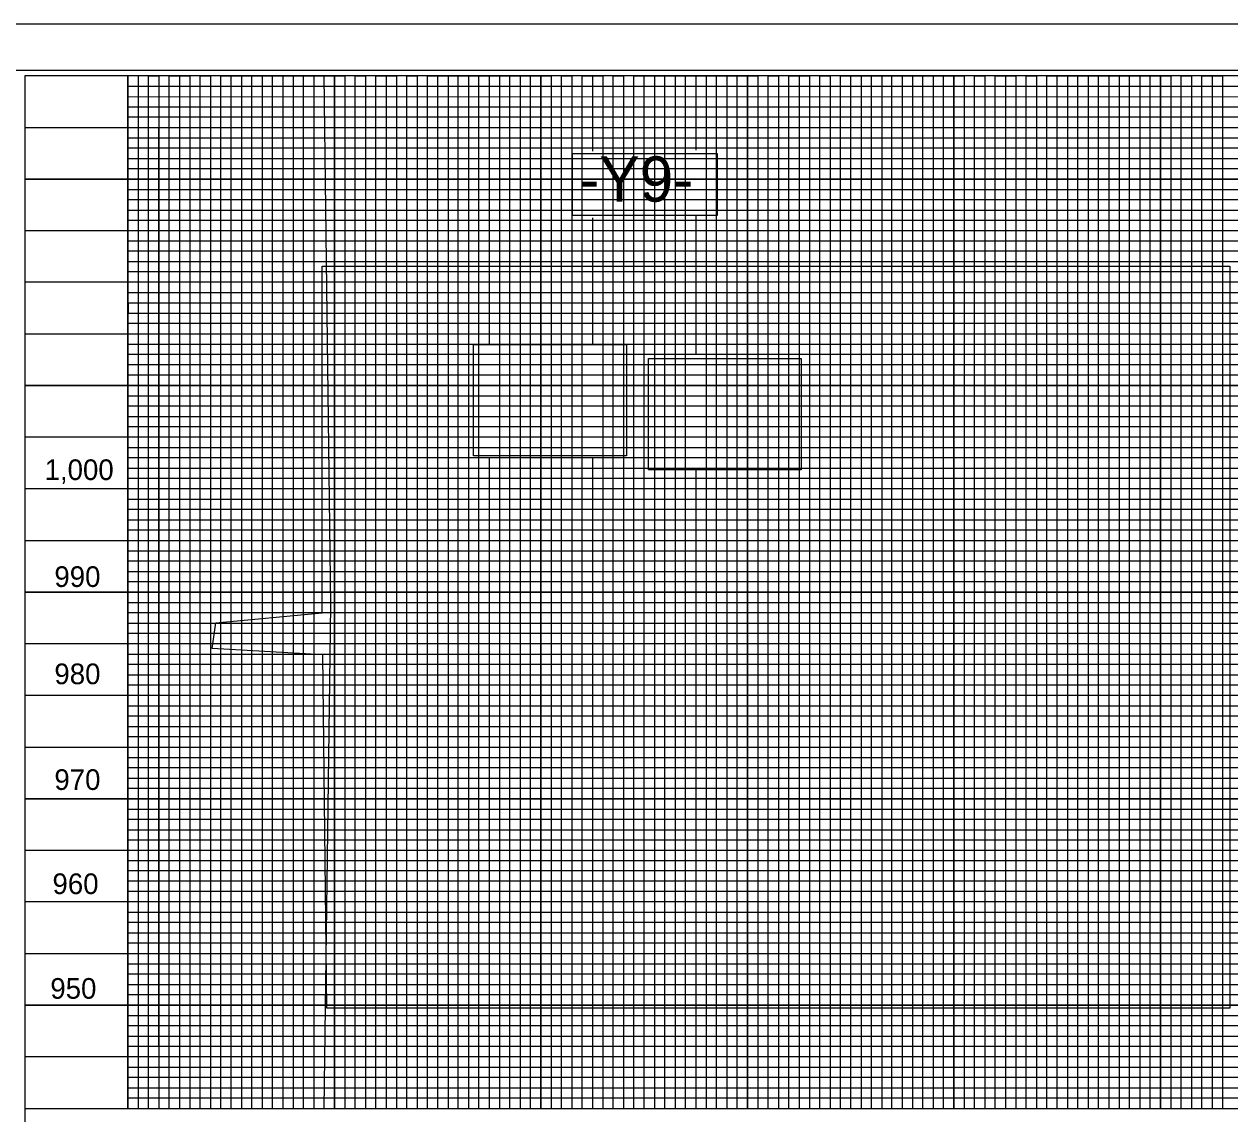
# Model space of a CAD drawing. Extents: x 1628636 to 1631253, y 896159 to 897520.
# Drawn here: x 1629226 to 1629810, y 896731 to 897259 of the extents above; entities that cross this region are included whole.
import ezdxf

# ---------------------------------------------------------------- set-up
doc = ezdxf.new("R2010")
doc.units = 0
for name, color, linetype in [('Prop DSN Text', 7, 'Continuous'), ('Prop PHM Black Shape', 7, 'Continuous'), ('Scratch_Level_6', 7, 'Continuous'), ('Sheet Cutting Line CELL', 7, 'Continuous'), ('Sheet DOT Grid CELL', 7, 'Continuous'), ('Sheet Layout Profile Border Port 1', 7, 'Continuous'), ('Sheet Plot Border Inside CELL', 7, 'Continuous'), ('Sheet Plot Border Outside CELL', 7, 'Continuous'), ('Sheet Profile CELL', 7, 'Continuous'), ('Sheet Profile Grid Major CELL', 7, 'Continuous'), ('Sheet Profile Grid Middle CELL', 7, 'Continuous'), ('Sheet Profile Grid Minor CELL', 7, 'Continuous')]:
    doc.layers.add(name, color=color, linetype=linetype)

msp = doc.modelspace()

# ---------------------------------------------------------------- linework, layer by layer
at = {"layer": 'Prop PHM Black Shape'}
for points in [[(1629491.77, 897196.22), (1629561.77, 897196.22), (1629561.77, 897166.22), (1629491.77, 897166.22)], [(1629443.84, 897103.79), (1629517.89, 897103.79), (1629517.89, 897049.92), (1629443.84, 897049.92)], [(1629528.51, 897096.99), (1629602.56, 897096.99), (1629602.56, 897043.11), (1629528.51, 897043.11)]]:
    msp.add_lwpolyline(points, close=True, dxfattribs=at)
at = {"layer": 'Scratch_Level_6'}
for points in [[(1629291.5, 897208.9), (1629781.5, 897208.9), (1629781.5, 896763.9), (1629291.5, 896763.9)], [(1629370.86, 896953.54), (1629317.29, 896956.57), (1629319.12, 896969.06), (1629370.56, 896973.83), (1629370.56, 897141.7), (1629810.05, 897141.7), (1629810.05, 896782.51), (1629372.86, 896782.51)]]:
    msp.add_lwpolyline(points, close=True, dxfattribs=at)
at = {"layer": 'Sheet Cutting Line CELL'}
msp.add_line((1630743.5, 897258.9), (1629059.5, 897258.9), dxfattribs=at)
at = {"layer": 'Sheet DOT Grid CELL'}
for p, q in [((1629276.5, 896733.9), (1629276.5, 897233.9)), ((1629326.5, 896733.9), (1629326.5, 897233.9)), ((1629376.5, 896733.9), (1629376.5, 897233.9)), ((1629426.5, 896733.9), (1629426.5, 897233.9)), ((1629476.5, 896733.9), (1629476.5, 897233.9)), ((1629526.5, 896733.9), (1629526.5, 897233.9)), ((1629576.5, 896733.9), (1629576.5, 897233.9)), ((1629626.5, 896733.9), (1629626.5, 897233.9)), ((1629676.5, 896733.9), (1629676.5, 897233.9)), ((1629726.5, 896733.9), (1629726.5, 897233.9)), ((1629776.5, 896733.9), (1629776.5, 897233.9)), ((1630526.45, 897183.9), (1629226.5, 897183.9)), ((1630526.45, 897133.9), (1629226.5, 897133.9)), ((1630526.5, 897083.9), (1629226.5, 897083.9)), ((1630726.5, 897033.9), (1629226.5, 897033.9)), ((1630726.5, 896983.9), (1629226.5, 896983.9)), ((1630726.5, 896933.9), (1629226.5, 896933.9)), ((1630726.5, 896883.9), (1629226.5, 896883.9)), ((1630726.5, 896833.9), (1629226.5, 896833.9)), ((1630726.5, 896783.9), (1629226.5, 896783.9))]:
    msp.add_line(p, q, dxfattribs=at)
at = {"layer": 'Sheet Layout Profile Border Port 1'}
msp.add_lwpolyline([(1629276.5, 897072.85), (1629276.5, 896733.9), (1630676.5, 896733.9), (1630676.5, 897072.85)], dxfattribs=at)
at = {"layer": 'Sheet Plot Border Inside CELL'}
msp.add_lwpolyline([(1629072.5, 896181.35), (1630739, 896181.35), (1630739, 897236.45), (1629072.5, 897236.45)], close=True, dxfattribs=at)
at = {"layer": 'Sheet Plot Border Outside CELL'}
msp.add_lwpolyline([(1629059.5, 896158.9), (1630743.5, 896158.9), (1630743.5, 897258.9), (1629059.5, 897258.9)], close=True, dxfattribs=at)
at = {"layer": 'Sheet Profile CELL'}
msp.add_line((1629226.5, 896733.9), (1630726.5, 896733.9), dxfattribs=at)
msp.add_lwpolyline([(1630726.5, 897233.9), (1629226.5, 897233.9), (1629226.5, 896183.9), (1630726.5, 896183.9)], close=True, dxfattribs=at)
at = {"layer": 'Sheet Profile Grid Major CELL'}
for points in [[(1629276.5, 897233.9), (1629276.5, 896733.9), (1629326.5, 896733.9), (1629326.5, 897233.9), (1629376.5, 897233.9), (1629376.5, 896733.9), (1629426.5, 896733.9), (1629426.5, 897233.9), (1629476.5, 897233.9), (1629476.5, 896733.9), (1629526.5, 896733.9), (1629526.5, 897233.9), (1629576.5, 897233.9), (1629576.5, 896733.9), (1629626.5, 896733.9), (1629626.5, 897233.9), (1629676.5, 897233.9), (1629676.5, 896733.9), (1629726.5, 896733.9), (1629726.5, 897233.9), (1629776.5, 897233.9), (1629776.5, 896733.9), (1629826.5, 896733.9)], [(1629226.5, 897183.9), (1630526.5, 897183.9)], [(1630526.5, 897133.9), (1629226.5, 897133.9), (1629226.5, 897083.9), (1630526.5, 897083.9)], [(1630726.5, 897033.9), (1629226.5, 897033.9), (1629226.5, 896983.9), (1630726.5, 896983.9)], [(1630726.5, 896933.9), (1629226.5, 896933.9), (1629226.5, 896883.9), (1630726.5, 896883.9)], [(1630726.5, 896833.9), (1629226.5, 896833.9), (1629226.5, 896833.9), (1629226.5, 896783.9), (1630726.5, 896783.9)]]:
    msp.add_lwpolyline(points, dxfattribs=at)
at = {"layer": 'Sheet Profile Grid Middle CELL'}
msp.add_line((1629226.5, 897208.9), (1630526.45, 897208.9), dxfattribs=at)
for points in [[(1630526.5, 897158.9), (1629226.5, 897158.9), (1629226.5, 897108.9), (1630526.5, 897108.9)], [(1630098.37, 897058.9), (1629226.5, 897058.9), (1629226.5, 897008.9), (1630551.5, 897008.9)], [(1630726.5, 896958.9), (1629226.5, 896958.9), (1629226.5, 896908.9), (1630726.5, 896908.9)], [(1630726.5, 896858.9), (1629226.5, 896858.9), (1629226.5, 896808.9), (1630726.5, 896808.9)], [(1630726.5, 896758.9), (1629226.5, 896758.9)]]:
    msp.add_lwpolyline(points, dxfattribs=at)
at = {"layer": 'Sheet Profile Grid Minor CELL'}
for p, q in [((1629281.5, 897233.9), (1629281.5, 896733.9)), ((1629286.5, 896733.9), (1629286.5, 897233.9)), ((1629286.5, 897233.9), (1629291.5, 897233.9)), ((1629291.5, 897233.9), (1629291.5, 896733.9)), ((1629296.5, 896733.9), (1629296.5, 897233.9)), ((1629296.5, 897233.9), (1629306.5, 897233.9)), ((1629301.5, 897233.9), (1629301.5, 896733.9)), ((1629306.5, 897233.9), (1629306.5, 896733.9)), ((1629311.5, 896733.9), (1629311.5, 897233.9)), ((1629311.5, 897233.9), (1629316.5, 897233.9)), ((1629316.5, 897233.9), (1629316.5, 896733.9)), ((1629336.5, 896733.9), (1629336.5, 897233.9)), ((1629336.5, 897233.9), (1629341.5, 897233.9)), ((1629341.5, 897233.9), (1629341.5, 896733.9)), ((1629346.5, 896733.9), (1629346.5, 897233.9)), ((1629346.5, 897233.9), (1629356.5, 897233.9)), ((1629351.5, 897233.9), (1629351.5, 896733.9)), ((1629356.5, 897233.9), (1629356.5, 896733.9)), ((1629361.5, 896733.9), (1629361.5, 897233.9)), ((1629361.5, 897233.9), (1629366.5, 897233.9)), ((1629366.5, 897233.9), (1629366.5, 896733.9)), ((1629371.5, 897233.9), (1629381.5, 897233.9)), ((1629381.5, 897233.9), (1629381.5, 896733.9)), ((1629386.5, 896733.9), (1629386.5, 897233.9)), ((1629386.5, 897233.9), (1629391.5, 897233.9)), ((1629391.5, 897233.9), (1629391.5, 896733.9)), ((1629396.5, 896733.9), (1629396.5, 897233.9)), ((1629396.5, 897233.9), (1629406.5, 897233.9)), ((1629401.5, 897233.9), (1629401.5, 896733.9)), ((1629406.5, 897233.9), (1629406.5, 896733.9)), ((1629411.5, 896733.9), (1629411.5, 897233.9)), ((1629411.5, 897233.9), (1629416.5, 897233.9)), ((1629416.5, 897233.9), (1629416.5, 896733.9)), ((1629421.5, 896733.9), (1629421.5, 897233.9)), ((1629421.5, 897233.9), (1629431.5, 897233.9)), ((1629431.5, 897233.9), (1629431.5, 896733.9)), ((1629436.5, 896733.9), (1629436.5, 897233.9)), ((1629436.5, 897233.9), (1629441.5, 897233.9)), ((1629441.5, 897233.9), (1629441.5, 896733.9)), ((1629446.5, 896733.9), (1629446.5, 897233.9)), ((1629446.5, 897233.9), (1629456.5, 897233.9)), ((1629451.5, 897233.9), (1629451.5, 897103.9)), ((1629456.5, 897233.9), (1629456.5, 896733.9)), ((1629461.5, 896733.9), (1629461.5, 897233.9)), ((1629461.5, 897233.9), (1629466.5, 897233.9)), ((1629466.5, 897233.9), (1629466.5, 896733.9)), ((1629471.5, 896733.9), (1629471.5, 897233.9)), ((1629471.5, 897233.9), (1629481.5, 897233.9)), ((1629481.5, 897233.9), (1629481.5, 896733.9)), ((1629486.5, 896733.9), (1629486.5, 897233.9)), ((1629486.5, 897233.9), (1629491.5, 897233.9)), ((1629491.5, 897233.9), (1629491.5, 896733.9)), ((1629496.5, 896733.9), (1629496.5, 897233.9)), ((1629496.5, 897233.9), (1629506.5, 897233.9)), ((1629501.5, 897233.9), (1629501.5, 897197.38)), ((1629506.5, 897233.9), (1629506.5, 896733.9)), ((1629511.5, 896733.9), (1629511.5, 897233.9)), ((1629511.5, 897233.9), (1629516.5, 897233.9)), ((1629516.5, 897233.9), (1629516.5, 896733.9)), ((1629521.5, 896733.9), (1629521.5, 897233.9)), ((1629521.5, 897233.9), (1629531.5, 897233.9)), ((1629531.5, 897233.9), (1629531.5, 896733.9)), ((1629536.5, 896733.9), (1629536.5, 897233.9)), ((1629536.5, 897233.9), (1629541.5, 897233.9)), ((1629541.5, 897233.9), (1629541.5, 896733.9)), ((1629546.5, 896733.9), (1629546.5, 897233.9)), ((1629546.5, 897233.9), (1629556.5, 897233.9)), ((1629551.5, 897233.9), (1629551.5, 897197.9)), ((1629556.5, 897233.9), (1629556.5, 896733.9)), ((1629561.5, 896733.9), (1629561.5, 897233.9)), ((1629561.5, 897233.9), (1629566.5, 897233.9)), ((1629566.5, 897233.9), (1629566.5, 896733.9)), ((1629571.5, 896733.9), (1629571.5, 897233.9)), ((1629571.5, 897233.9), (1629581.5, 897233.9)), ((1629581.5, 897233.9), (1629581.5, 896733.9)), ((1629586.5, 896733.9), (1629586.5, 897233.9)), ((1629586.5, 897233.9), (1629591.5, 897233.9)), ((1629591.5, 897233.9), (1629591.5, 896733.9)), ((1629596.5, 896733.9), (1629596.5, 897233.9)), ((1629596.5, 897233.9), (1629606.5, 897233.9)), ((1629601.5, 897233.9), (1629601.5, 896733.9)), ((1629606.5, 897233.9), (1629606.5, 896733.9)), ((1629611.5, 896733.9), (1629611.5, 897233.9)), ((1629611.5, 897233.9), (1629616.5, 897233.9)), ((1629616.5, 897233.9), (1629616.5, 896733.9)), ((1629621.5, 896733.9), (1629621.5, 897233.9)), ((1629621.5, 897233.9), (1629631.5, 897233.9)), ((1629631.5, 897233.9), (1629631.5, 896733.9)), ((1629636.5, 896733.9), (1629636.5, 897233.9)), ((1629636.5, 897233.9), (1629641.5, 897233.9)), ((1629641.5, 897233.9), (1629641.5, 896733.9)), ((1629646.5, 896733.9), (1629646.5, 897233.9)), ((1629646.5, 897233.9), (1629656.5, 897233.9)), ((1629651.5, 897233.9), (1629651.5, 896733.9)), ((1629656.5, 897233.9), (1629656.5, 896733.9)), ((1629661.5, 896733.9), (1629661.5, 897233.9)), ((1629661.5, 897233.9), (1629666.5, 897233.9)), ((1629666.5, 897233.9), (1629666.5, 896733.9)), ((1629671.5, 896733.9), (1629671.5, 897233.9)), ((1629671.5, 897233.9), (1629681.5, 897233.9)), ((1629681.5, 897233.9), (1629681.5, 896733.9)), ((1629686.5, 896733.9), (1629686.5, 897233.9)), ((1629686.5, 897233.9), (1629691.5, 897233.9)), ((1629691.5, 897233.9), (1629691.5, 896733.9)), ((1629696.5, 896733.9), (1629696.5, 897233.9)), ((1629696.5, 897233.9), (1629706.5, 897233.9)), ((1629701.5, 897233.9), (1629701.5, 896733.9)), ((1629706.5, 897233.9), (1629706.5, 896733.9)), ((1629711.5, 896733.9), (1629711.5, 897233.9)), ((1629711.5, 897233.9), (1629716.5, 897233.9)), ((1629716.5, 897233.9), (1629716.5, 896733.9)), ((1629721.5, 896733.9), (1629721.5, 897233.9)), ((1629721.5, 897233.9), (1629731.5, 897233.9)), ((1629731.5, 897233.9), (1629731.5, 896733.9)), ((1629736.5, 896733.9), (1629736.5, 897233.9)), ((1629736.5, 897233.9), (1629741.5, 897233.9)), ((1629741.5, 897233.9), (1629741.5, 896733.9)), ((1629746.5, 896733.9), (1629746.5, 897233.9)), ((1629746.5, 897233.9), (1629756.5, 897233.9)), ((1629751.5, 897233.9), (1629751.5, 896733.9)), ((1629756.5, 897233.9), (1629756.5, 896733.9)), ((1629761.5, 896733.9), (1629761.5, 897233.9)), ((1629761.5, 897233.9), (1629766.5, 897233.9)), ((1629766.5, 897233.9), (1629766.5, 896733.9)), ((1629771.5, 896733.9), (1629771.5, 897233.9)), ((1629771.5, 897233.9), (1629781.5, 897233.9)), ((1629781.5, 897233.9), (1629781.5, 896733.9)), ((1629786.5, 896733.9), (1629786.5, 897233.9)), ((1629786.5, 897233.9), (1629791.5, 897233.9)), ((1629791.5, 897233.9), (1629791.5, 896733.9)), ((1629796.5, 896733.9), (1629796.5, 897233.9)), ((1629796.5, 897233.9), (1629806.5, 897233.9)), ((1629801.5, 897233.9), (1629801.5, 896733.9)), ((1629806.5, 897233.9), (1629806.5, 896733.9)), ((1629276.5, 897228.9), (1630526.5, 897228.9)), ((1629276.5, 897223.9), (1629276.5, 897223.9)), ((1630526.5, 897223.9), (1629276.5, 897223.55)), ((1629276.5, 897218.9), (1630526.5, 897218.9)), ((1629501.5, 897165.19), (1629501.5, 897103.9)), ((1629551.5, 897166.23), (1629551.5, 897098.9)), ((1630526.45, 897098.9), (1629276.5, 897098.9)), ((1630526.5, 897093.9), (1629276.5, 897093.9)), ((1630101.43, 897088.9), (1629276.5, 897088.9)), ((1629276.5, 897078.9), (1630101.43, 897078.9)), ((1630101.43, 897073.9), (1629276.5, 897073.9)), ((1629276.5, 897068.9), (1630101.5, 897068.9)), ((1630101.43, 897048.9), (1629276.5, 897048.9)), ((1629451.5, 897048.9), (1629451.5, 896733.9)), ((1629501.5, 897048.97), (1629501.5, 896733.9)), ((1629276.5, 897043.9), (1630171.5, 897043.9)), ((1629551.5, 897043.9), (1629551.5, 896733.9)), ((1630676.5, 897023.9), (1629276.5, 897023.9)), ((1629276.5, 897018.9), (1630676.5, 897018.9)), ((1630676.5, 896998.9), (1629276.5, 896998.9)), ((1629276.5, 896993.9), (1630676.5, 896993.9)), ((1630676.5, 896988.9), (1629276.5, 896988.9)), ((1629276.5, 896978.9), (1630676.5, 896978.9)), ((1630676.5, 896973.9), (1629276.5, 896973.9)), ((1629276.5, 896968.9), (1630676.5, 896968.9)), ((1630676.5, 896963.9), (1629276.5, 896963.9)), ((1629276.5, 896953.9), (1630676.5, 896953.9)), ((1630676.5, 896948.9), (1629276.5, 896948.9)), ((1629276.5, 896943.9), (1630676.5, 896943.9)), ((1630676.5, 896938.9), (1629276.5, 896938.9)), ((1629276.5, 896928.9), (1630676.5, 896928.9)), ((1630676.5, 896923.9), (1629276.5, 896923.9)), ((1629276.5, 896918.9), (1630676.5, 896918.9)), ((1630676.5, 896913.9), (1629276.5, 896913.9)), ((1629276.5, 896903.9), (1630676.5, 896903.9)), ((1630676.5, 896898.9), (1629276.5, 896898.9)), ((1629276.5, 896893.9), (1630676.5, 896893.9)), ((1630676.5, 896888.9), (1629276.5, 896888.9)), ((1629276.5, 896878.9), (1630676.5, 896878.9)), ((1630676.5, 896873.9), (1629276.5, 896873.9)), ((1629276.5, 896868.9), (1630676.5, 896868.9)), ((1630676.5, 896863.9), (1629276.5, 896863.9)), ((1629276.5, 896853.9), (1630676.5, 896853.9)), ((1630676.5, 896848.9), (1629276.5, 896848.9)), ((1630676.5, 896843.9), (1629276.5, 896843.9)), ((1630676.5, 896838.9), (1629276.5, 896838.9)), ((1629276.5, 896828.9), (1630676.5, 896828.9)), ((1630676.5, 896823.9), (1629276.5, 896823.9)), ((1629276.5, 896818.9), (1630676.5, 896818.9)), ((1630676.5, 896813.9), (1629276.5, 896813.9)), ((1629276.5, 896803.9), (1630676.5, 896803.9)), ((1630676.5, 896798.9), (1629276.5, 896798.9)), ((1629276.5, 896793.9), (1630676.5, 896793.9)), ((1630676.5, 896788.9), (1629276.5, 896788.9)), ((1629276.5, 896778.9), (1630676.5, 896778.9)), ((1630676.5, 896773.9), (1629276.5, 896773.9)), ((1629276.5, 896768.9), (1630676.5, 896768.9)), ((1630676.5, 896763.9), (1629276.5, 896763.9)), ((1629276.5, 896753.9), (1630676.5, 896753.9)), ((1630676.5, 896748.9), (1629276.5, 896748.9)), ((1629276.5, 896743.9), (1630676.5, 896743.9)), ((1629281.5, 896733.9), (1629286.5, 896733.9)), ((1629291.5, 896733.9), (1629296.5, 896733.9)), ((1629306.5, 896733.9), (1629311.5, 896733.9)), ((1629316.5, 896733.9), (1629321.5, 896733.9)), ((1629321.5, 896733.9), (1629331.5, 896733.9)), ((1629331.5, 896733.9), (1629336.5, 896733.9)), ((1629341.5, 896733.9), (1629346.5, 896733.9)), ((1629356.5, 896733.9), (1629361.5, 896733.9)), ((1629366.5, 896733.9), (1629371.5, 896733.9)), ((1629381.5, 896733.9), (1629386.5, 896733.9)), ((1629391.5, 896733.9), (1629396.5, 896733.9)), ((1629406.5, 896733.9), (1629411.5, 896733.9)), ((1629416.5, 896733.9), (1629421.5, 896733.9)), ((1629431.5, 896733.9), (1629436.5, 896733.9)), ((1629441.5, 896733.9), (1629446.5, 896733.9)), ((1629456.5, 896733.9), (1629461.5, 896733.9)), ((1629466.5, 896733.9), (1629471.5, 896733.9)), ((1629481.5, 896733.9), (1629486.5, 896733.9)), ((1629491.5, 896733.9), (1629496.5, 896733.9)), ((1629506.5, 896733.9), (1629511.5, 896733.9)), ((1629516.5, 896733.9), (1629521.5, 896733.9)), ((1629531.5, 896733.9), (1629536.5, 896733.9)), ((1629541.5, 896733.9), (1629546.5, 896733.9)), ((1629556.5, 896733.9), (1629561.5, 896733.9)), ((1629566.5, 896733.9), (1629571.5, 896733.9)), ((1629581.5, 896733.9), (1629586.5, 896733.9)), ((1629591.5, 896733.9), (1629596.5, 896733.9)), ((1629606.5, 896733.9), (1629611.5, 896733.9)), ((1629616.5, 896733.9), (1629621.5, 896733.9)), ((1629631.5, 896733.9), (1629636.5, 896733.9)), ((1629641.5, 896733.9), (1629646.5, 896733.9)), ((1629656.5, 896733.9), (1629661.5, 896733.9)), ((1629666.5, 896733.9), (1629671.5, 896733.9)), ((1629681.5, 896733.9), (1629686.5, 896733.9)), ((1629691.5, 896733.9), (1629696.5, 896733.9)), ((1629706.5, 896733.9), (1629711.5, 896733.9)), ((1629716.5, 896733.9), (1629721.5, 896733.9)), ((1629731.5, 896733.9), (1629736.5, 896733.9)), ((1629741.5, 896733.9), (1629746.5, 896733.9)), ((1629756.5, 896733.9), (1629761.5, 896733.9)), ((1629766.5, 896733.9), (1629771.5, 896733.9)), ((1629781.5, 896733.9), (1629786.5, 896733.9)), ((1629791.5, 896733.9), (1629796.5, 896733.9)), ((1629806.5, 896733.9), (1629811.5, 896733.9))]:
    msp.add_line(p, q, dxfattribs=at)
for points in [[(1629321.5, 896733.9), (1629321.5, 897233.9), (1629331.5, 897233.9), (1629331.5, 896733.9)], [(1629371.5, 896733.9), (1629374.8, 896977.47), (1629371.5, 897233.9)], [(1630526.5, 897213.9), (1629276.5, 897213.9), (1629276.5, 897203.9), (1630526.5, 897203.9)], [(1630526.45, 897198.9), (1629276.5, 897198.9), (1629276.5, 897193.9), (1630526.5, 897193.9)], [(1630526.5, 897188.9), (1629276.5, 897188.9), (1629276.5, 897178.9), (1630526.5, 897178.9)], [(1630526.5, 897173.9), (1629276.5, 897173.9), (1629276.5, 897168.9), (1630526.5, 897168.9)], [(1630526.5, 897163.9), (1629276.5, 897163.9), (1629276.5, 897153.9), (1630526.5, 897153.9)], [(1630526.5, 897148.9), (1629276.5, 897148.9), (1629276.5, 897143.9), (1630526.5, 897143.9)], [(1630526.5, 897138.9), (1629276.5, 897138.9), (1629276.5, 897128.9), (1630526.5, 897128.9)], [(1630526.5, 897123.8), (1629276.6, 897123.8), (1629276.6, 897118.9), (1630526.5, 897118.9)], [(1630526.5, 897113.9), (1629276.5, 897113.9), (1629276.5, 897103.9), (1630526.5, 897103.9)], [(1630101.43, 897063.9), (1629276.5, 897063.9), (1629276.5, 897053.9), (1630101.43, 897053.9)], [(1630676.5, 897038.9), (1629276.5, 897038.9), (1629276.5, 897028.9), (1630676.5, 897028.9)], [(1630676.5, 897013.9), (1629276.5, 897013.9), (1629276.5, 897003.9), (1630676.5, 897003.9)], [(1630676.5, 896738.9), (1629276.5, 896738.9)]]:
    msp.add_lwpolyline(points, dxfattribs=at)

# ---------------------------------------------------------------- texts
at = {"layer": 'Prop DSN Text'}
for s, height, p in [('-Y9-', 21.875, (1629495.05, 897172.96)), ('1,000', 10, (1629236.15, 897038.17)), ('990', 10, (1629240.89, 896986.41)), ('980', 10, (1629240.89, 896939.33)), ('970', 10, (1629240.89, 896888.14)), ('960', 10, (1629239.97, 896837.72)), ('950', 10, (1629238.93, 896787.05))]:
    msp.add_text(s, height=height, dxfattribs=at).set_placement(p)

doc.saveas('drawing.dxf')
